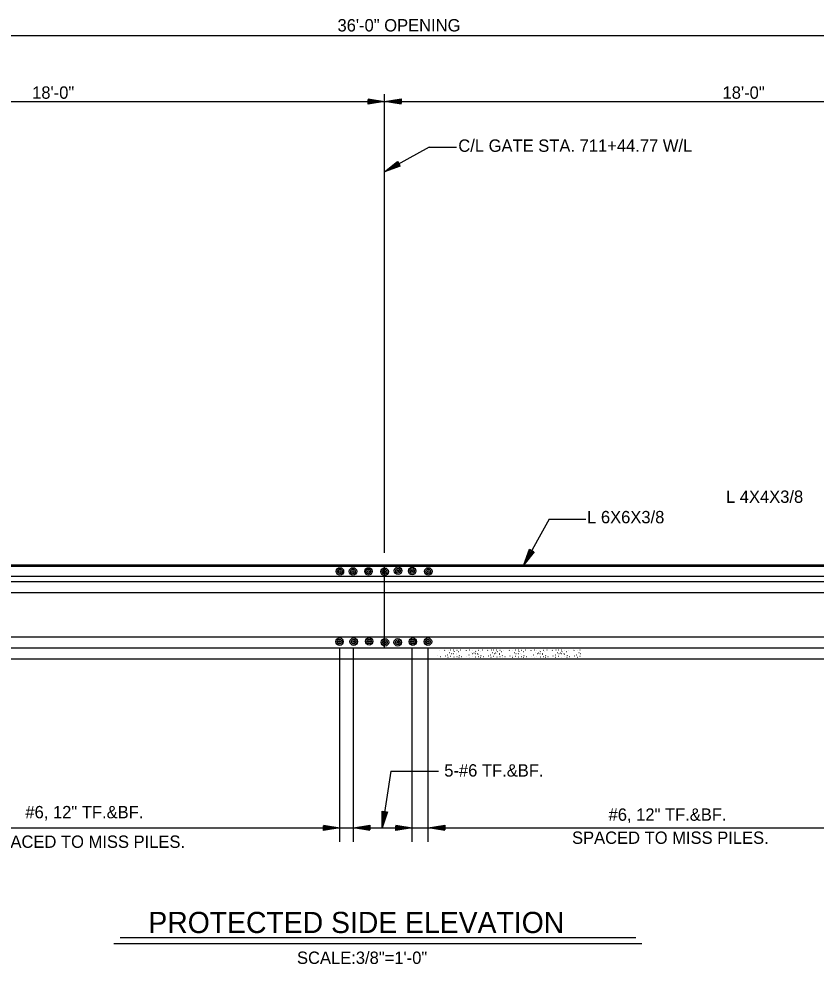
# Model space of a CAD drawing. Extents: x 6 to 106, y 3 to 74.
# Drawn here: x 30.14 to 54.21, y 4.97 to 33.52 of the extents above; entities that cross this region are included whole.
import ezdxf

# ---------------------------------------------------------------- set-up
doc = ezdxf.new("R2010")
doc.units = 0
for name, color, linetype in [('Level 2', 7, 'Continuous'), ('Level 22', 7, 'Continuous'), ('Level 25', 7, 'Continuous'), ('Level 44', 7, 'Continuous'), ('Level 50', 7, 'Continuous')]:
    doc.layers.add(name, color=color, linetype=linetype)

msp = doc.modelspace()

# ---------------------------------------------------------------- linework, layer by layer
at = {"layer": 'Level 22'}
for p, q in [((42.533, 29.648), (41.18, 28.901)), ((42.533, 29.648), (43.351, 29.648)), ((46.146, 18.409), (45.391, 17.023)), ((46.146, 18.409), (47.259, 18.409)), ((41.374, 10.791), (41.11, 9.085)), ((33.204, 5.775), (48.764, 5.775)), ((33.014, 5.59), (48.952, 5.59))]:
    msp.add_line(p, q, dxfattribs=at)
at = {"layer": 'Level 25'}
for p, q in [((23.18, 33.023), (59.18, 33.023)), ((41.18, 17.389), (41.18, 31.247)), ((23.18, 31.023), (41.18, 31.023)), ((41.18, 31.023), (59.18, 31.023)), ((14.719, 17.023), (67.642, 17.023)), ((23.18, 16.992), (59.18, 16.992)), ((41.18, 14.523), (41.18, 17.023)), ((16.1, 16.69), (66.145, 16.69)), ((23.18, 16.523), (59.18, 16.523)), ((14.719, 16.19), (67.642, 16.19)), ((16.119, 14.856), (66.126, 14.856)), ((14.719, 14.523), (67.642, 14.523)), ((39.833, 8.658), (39.833, 14.523)), ((40.241, 8.658), (40.241, 14.523)), ((42.02, 8.658), (42.02, 14.523)), ((42.501, 8.658), (42.501, 14.523)), ((14.719, 14.19), (67.642, 14.19)), ((41.374, 10.791), (42.815, 10.791)), ((25.685, 9.085), (40.241, 9.085)), ((40.241, 9.085), (42.02, 9.085)), ((42.02, 9.085), (56.676, 9.085))]:
    msp.add_line(p, q, dxfattribs=at)
at = {"layer": 'Level 44'}
for p, q in [((42.792, 14.284), (42.788, 14.284)), ((42.834, 14.454), (42.826, 14.453)), ((42.998, 14.448), (42.991, 14.444)), ((43.084, 14.304), (43.076, 14.303)), ((43.105, 14.454), (43.098, 14.453)), ((43.15, 14.371), (43.142, 14.37)), ((43.179, 14.449), (43.172, 14.448)), ((43.198, 14.337), (43.189, 14.337)), ((43.235, 14.361), (43.228, 14.36)), ((43.269, 14.451), (43.262, 14.451)), ((43.274, 14.34), (43.267, 14.34)), ((43.286, 14.405), (43.279, 14.404)), ((43.347, 14.34), (43.339, 14.34)), ((43.357, 14.321), (43.35, 14.32)), ((43.372, 14.439), (43.365, 14.439)), ((43.421, 14.398), (43.414, 14.397)), ((43.443, 14.284), (43.436, 14.283)), ((43.485, 14.454), (43.477, 14.453)), ((43.649, 14.448), (43.641, 14.444)), ((43.734, 14.304), (43.727, 14.303)), ((43.756, 14.454), (43.749, 14.453)), ((43.8, 14.371), (43.793, 14.37)), ((43.83, 14.449), (43.822, 14.448)), ((43.849, 14.337), (43.84, 14.337)), ((43.886, 14.361), (43.879, 14.36)), ((43.92, 14.451), (43.913, 14.451)), ((43.925, 14.34), (43.918, 14.34)), ((43.937, 14.405), (43.93, 14.404)), ((43.998, 14.34), (43.99, 14.34)), ((44.008, 14.321), (44.001, 14.32)), ((44.023, 14.439), (44.016, 14.439)), ((44.072, 14.398), (44.065, 14.397)), ((44.094, 14.284), (44.087, 14.283)), ((44.135, 14.454), (44.128, 14.453)), ((44.3, 14.448), (44.292, 14.444)), ((44.385, 14.304), (44.378, 14.303)), ((44.407, 14.454), (44.4, 14.453)), ((44.451, 14.371), (44.444, 14.37)), ((44.481, 14.449), (44.473, 14.448)), ((44.5, 14.337), (44.491, 14.337)), ((44.537, 14.361), (44.53, 14.36)), ((44.571, 14.451), (44.564, 14.451)), ((44.576, 14.34), (44.569, 14.34)), ((44.588, 14.405), (44.581, 14.404)), ((44.649, 14.34), (44.64, 14.34)), ((44.659, 14.321), (44.652, 14.32)), ((44.674, 14.439), (44.666, 14.439)), ((44.723, 14.398), (44.715, 14.397)), ((44.745, 14.284), (44.737, 14.283)), ((44.786, 14.454), (44.779, 14.453)), ((44.951, 14.448), (44.943, 14.444)), ((45.036, 14.304), (45.029, 14.303)), ((45.058, 14.454), (45.051, 14.453)), ((45.102, 14.371), (45.095, 14.37)), ((45.131, 14.449), (45.124, 14.448)), ((45.15, 14.337), (45.141, 14.337)), ((45.188, 14.361), (45.18, 14.36)), ((45.222, 14.451), (45.215, 14.451)), ((45.227, 14.34), (45.219, 14.34)), ((45.239, 14.405), (45.232, 14.404)), ((45.3, 14.34), (45.291, 14.34)), ((45.31, 14.321), (45.303, 14.32)), ((45.325, 14.439), (45.317, 14.439)), ((45.374, 14.398), (45.366, 14.397)), ((45.396, 14.284), (45.388, 14.283)), ((45.437, 14.454), (45.43, 14.453)), ((45.602, 14.448), (45.594, 14.444)), ((45.687, 14.304), (45.68, 14.303)), ((45.709, 14.454), (45.701, 14.453)), ((45.753, 14.371), (45.746, 14.37)), ((45.782, 14.449), (45.775, 14.448)), ((45.801, 14.337), (45.792, 14.337)), ((45.839, 14.361), (45.831, 14.36)), ((45.873, 14.451), (45.865, 14.451)), ((45.878, 14.34), (45.87, 14.34)), ((45.89, 14.405), (45.882, 14.404)), ((45.95, 14.34), (45.942, 14.34)), ((45.961, 14.321), (45.953, 14.32)), ((45.975, 14.439), (45.968, 14.439)), ((46.024, 14.398), (46.017, 14.397)), ((46.046, 14.284), (46.039, 14.283)), ((46.088, 14.454), (46.081, 14.453)), ((46.253, 14.448), (46.245, 14.444)), ((46.338, 14.304), (46.33, 14.303)), ((46.36, 14.454), (46.352, 14.453)), ((46.404, 14.371), (46.396, 14.37)), ((46.433, 14.449), (46.426, 14.448)), ((46.452, 14.337), (46.443, 14.337)), ((46.489, 14.361), (46.482, 14.36)), ((46.524, 14.451), (46.516, 14.451)), ((46.529, 14.34), (46.521, 14.34)), ((46.541, 14.405), (46.533, 14.404)), ((46.601, 14.34), (46.593, 14.34)), ((46.612, 14.321), (46.604, 14.32)), ((46.626, 14.439), (46.619, 14.439)), ((46.675, 14.398), (46.668, 14.397)), ((46.697, 14.284), (46.69, 14.283)), ((46.739, 14.454), (46.731, 14.453)), ((46.903, 14.448), (46.896, 14.444)), ((46.989, 14.304), (46.981, 14.303)), ((47.01, 14.454), (47.003, 14.453)), ((47.055, 14.371), (47.047, 14.37)), ((47.084, 14.449), (47.077, 14.448)), ((47.103, 14.337), (47.094, 14.337)), ((42.866, 14.247), (42.857, 14.248)), ((43.017, 14.265), (43.01, 14.264)), ((43.098, 14.225), (43.091, 14.225)), ((43.179, 14.255), (43.172, 14.254)), ((43.282, 14.243), (43.274, 14.242)), ((43.372, 14.25), (43.365, 14.249)), ((43.436, 14.228), (43.428, 14.227)), ((43.517, 14.247), (43.508, 14.248)), ((43.668, 14.265), (43.661, 14.264)), ((43.749, 14.225), (43.742, 14.225)), ((43.83, 14.255), (43.822, 14.254)), ((43.933, 14.243), (43.925, 14.242)), ((44.023, 14.25), (44.016, 14.249)), ((44.087, 14.228), (44.079, 14.227)), ((44.168, 14.247), (44.159, 14.248)), ((44.319, 14.265), (44.312, 14.264)), ((44.4, 14.225), (44.392, 14.225)), ((44.481, 14.255), (44.473, 14.254)), ((44.583, 14.243), (44.576, 14.242)), ((44.674, 14.25), (44.666, 14.249)), ((44.737, 14.228), (44.73, 14.227)), ((44.819, 14.247), (44.81, 14.248)), ((44.97, 14.265), (44.963, 14.264)), ((45.051, 14.225), (45.043, 14.225)), ((45.131, 14.255), (45.124, 14.254)), ((45.234, 14.243), (45.227, 14.242)), ((45.325, 14.25), (45.317, 14.249)), ((45.388, 14.228), (45.381, 14.227)), ((45.469, 14.247), (45.461, 14.248)), ((45.621, 14.265), (45.613, 14.264)), ((45.701, 14.225), (45.694, 14.225)), ((45.782, 14.255), (45.775, 14.254)), ((45.885, 14.243), (45.878, 14.242)), ((45.975, 14.25), (45.968, 14.249)), ((46.039, 14.228), (46.032, 14.227)), ((46.12, 14.247), (46.112, 14.248)), ((46.272, 14.265), (46.264, 14.264)), ((46.352, 14.225), (46.345, 14.225)), ((46.433, 14.255), (46.426, 14.254)), ((46.536, 14.243), (46.529, 14.242)), ((46.626, 14.25), (46.619, 14.249)), ((46.69, 14.228), (46.683, 14.227)), ((46.771, 14.247), (46.762, 14.248)), ((46.922, 14.265), (46.915, 14.264)), ((47.003, 14.225), (46.996, 14.225)), ((47.084, 14.255), (47.077, 14.254))]:
    msp.add_line(p, q, dxfattribs=at)
at = {"layer": 'Level 50'}
for p, q in [((41.042, 31.023), (41.042, 31.023)), ((41.18, 31.023), (41.18, 31.023)), ((41.18, 31.023), (41.18, 31.023)), ((41.319, 31.023), (41.319, 31.023)), ((41.18, 28.901), (41.18, 28.901)), ((41.302, 28.968), (41.302, 28.968)), ((45.457, 17.145), (45.457, 17.145)), ((45.391, 17.023), (45.391, 17.023)), ((41.132, 9.222), (41.132, 9.222)), ((39.694, 9.085), (39.694, 9.085)), ((39.833, 9.085), (39.833, 9.085)), ((40.241, 9.085), (40.241, 9.085)), ((40.38, 9.085), (40.38, 9.085)), ((41.11, 9.085), (41.11, 9.085)), ((41.882, 9.085), (41.882, 9.085)), ((42.02, 9.085), (42.02, 9.085)), ((42.501, 9.085), (42.501, 9.085)), ((42.64, 9.085), (42.64, 9.085))]:
    msp.add_line(p, q, dxfattribs=at)
for points in [[(40.682, 31.106), (41.18, 31.023), (40.682, 30.94), (40.682, 31.082), (41.042, 31.023), (40.703, 30.967), (40.703, 31.058), (40.908, 31.023), (40.724, 30.994), (40.724, 31.031), (40.77, 31.023)], [(41.679, 30.94), (41.18, 31.023), (41.679, 31.106), (41.679, 30.964), (41.319, 31.023), (41.658, 31.079), (41.658, 30.988), (41.452, 31.023), (41.636, 31.052), (41.636, 31.015), (41.591, 31.023)], [(41.657, 29.069), (41.18, 28.901), (41.577, 29.214), (41.645, 29.09), (41.302, 28.968), (41.571, 29.181), (41.615, 29.101), (41.419, 29.032), (41.565, 29.147), (41.583, 29.114), (41.54, 29.099)], [(45.702, 17.421), (45.391, 17.023), (45.557, 17.5), (45.681, 17.433), (45.457, 17.145), (45.57, 17.469), (45.65, 17.426), (45.521, 17.262), (45.583, 17.437), (45.616, 17.42), (45.587, 17.384)], [(41.268, 9.565), (41.11, 9.085), (41.105, 9.59), (41.244, 9.569), (41.132, 9.222), (41.128, 9.565), (41.217, 9.551), (41.152, 9.354), (41.151, 9.54), (41.188, 9.534), (41.173, 9.491)], [(39.334, 9.168), (39.833, 9.085), (39.334, 9.002), (39.334, 9.144), (39.694, 9.085), (39.355, 9.029), (39.355, 9.12), (39.561, 9.085), (39.377, 9.056), (39.377, 9.093), (39.422, 9.085)], [(40.74, 9.002), (40.241, 9.085), (40.74, 9.168), (40.74, 9.026), (40.38, 9.085), (40.719, 9.141), (40.719, 9.05), (40.513, 9.085), (40.697, 9.114), (40.697, 9.077), (40.652, 9.085)], [(41.522, 9.168), (42.02, 9.085), (41.522, 9.002), (41.522, 9.144), (41.882, 9.085), (41.543, 9.029), (41.543, 9.12), (41.748, 9.085), (41.564, 9.056), (41.564, 9.093), (41.61, 9.085)], [(43, 9.002), (42.501, 9.085), (43, 9.168), (43, 9.026), (42.64, 9.085), (42.979, 9.141), (42.979, 9.05), (42.773, 9.085), (42.957, 9.114), (42.957, 9.077), (42.912, 9.085)]]:
    msp.add_lwpolyline(points, dxfattribs=at)
for centre, radius in [((39.834, 16.829), 0.113), ((39.834, 16.829), 0.0703), ((39.834, 16.829), 0.0281), ((40.229, 16.829), 0.113), ((40.229, 16.829), 0.0703), ((40.229, 16.829), 0.0281), ((40.696, 16.829), 0.113), ((40.696, 16.829), 0.0703), ((40.696, 16.829), 0.0281), ((41.183, 16.819), 0.113), ((41.183, 16.819), 0.0703), ((41.183, 16.819), 0.0281), ((41.589, 16.85), 0.113), ((41.589, 16.85), 0.0703), ((41.589, 16.85), 0.0281), ((42.015, 16.84), 0.113), ((42.015, 16.84), 0.0703), ((42.015, 16.84), 0.0281), ((42.503, 16.829), 0.113), ((42.503, 16.829), 0.0703), ((42.503, 16.829), 0.0281), ((39.823, 14.707), 0.113), ((39.823, 14.707), 0.0703), ((39.823, 14.707), 0.0281), ((40.25, 14.707), 0.113), ((40.25, 14.707), 0.0703), ((40.25, 14.707), 0.0281), ((40.717, 14.717), 0.113), ((40.717, 14.717), 0.0703), ((40.717, 14.717), 0.0281), ((41.193, 14.687), 0.113), ((41.193, 14.687), 0.0703), ((41.193, 14.687), 0.0281), ((41.579, 14.687), 0.113), ((41.579, 14.687), 0.0703), ((41.579, 14.687), 0.0281), ((42.036, 14.707), 0.113), ((42.036, 14.707), 0.0703), ((42.036, 14.707), 0.0281), ((42.492, 14.707), 0.113), ((42.492, 14.707), 0.0703), ((42.492, 14.707), 0.0281)]:
    msp.add_circle(centre, radius, dxfattribs=at)

# ---------------------------------------------------------------- texts
at = {"layer": 'Level 2'}
msp.add_text('PROTECTED SIDE ELEVATION', height=0.63999, dxfattribs=at).set_placement((34.051, 5.905))
at = {"layer": 'Level 22'}
for s, height, p in [('36\'-0" OPENING', 0.37333, (39.761, 33.14)), ('18\'-0"', 0.3733, (30.543, 31.107)), ('18\'-0"', 0.3733, (51.385, 31.107)), ('C/L GATE STA. 711+44.77 W/L', 0.37333, (43.408, 29.504)), ('L 4X4X3/8', 0.3733, (51.488, 18.9)), ('L 6X6X3/8', 0.3733, (47.297, 18.283)), ('5-#6 TF.&BF.', 0.37333, (42.984, 10.631)), ('#6, 12" TF.&BF.', 0.37333, (30.339, 9.371)), ('#6, 12" TF.&BF.', 0.37333, (47.944, 9.297)), ('SPACED TO MISS PILES.', 0.37333, (29.222, 8.478)), ('SPACED TO MISS PILES.', 0.37333, (46.841, 8.599)), ('SCALE:3/8"=1\'-0"', 0.37333, (38.538, 4.972))]:
    msp.add_text(s, height=height, dxfattribs=at).set_placement(p)

doc.saveas('drawing.dxf')
